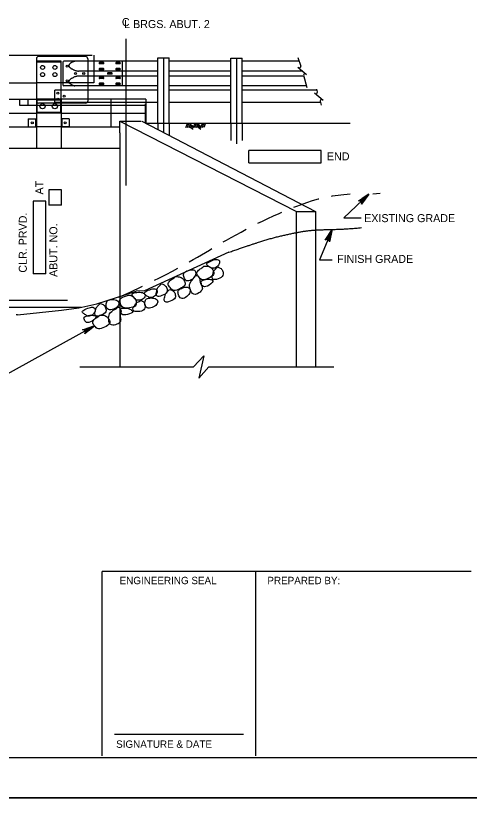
# Model space of a CAD drawing. Extents: x 638268 to 640277, y 295465 to 298435.
# Drawn here: x 638721.7 to 638891.9, y 297240 to 297540.5 of the extents above; entities that cross this region are included whole.
import ezdxf

# ---------------------------------------------------------------- set-up
doc = ezdxf.new("R2010")
doc.units = 0
for name, color, linetype in [('10', 7, 'Continuous'), ('2', 7, 'Continuous'), ('3', 7, 'Continuous'), ('4', 7, 'Continuous'), ('8', 7, 'Continuous'), ('Level 25', 7, 'Continuous'), ('PLT-BNDY', 7, 'Continuous')]:
    doc.layers.add(name, color=color, linetype=linetype)

msp = doc.modelspace()

# ---------------------------------------------------------------- linework, layer by layer
at = {"layer": '2'}
for p, q in [((638577.23, 297525.9), (638750.23, 297525.9)), ((638750.88, 297525.9), (638750.88, 297523.59)), ((638738.57, 297523.59), (638729.33, 297523.59)), ((638729.33, 297523.59), (638729.33, 297509.34)), ((638738.57, 297523.21), (638729.33, 297523.21)), ((638738.57, 297509.34), (638738.57, 297523.59)), ((638739.3, 297523.23), (638739.3, 297514.73)), ((638750.88, 297523.6), (638739.67, 297523.6)), ((638761.47, 297523.6), (638750.88, 297523.6)), ((638750.88, 297523.59), (638750.88, 297515.51)), ((638754.49, 297523.09), (638753.02, 297523.09)), ((638760.67, 297523.09), (638759.19, 297523.09)), ((638761.54, 297523.6), (638761.54, 297514.36)), ((638774.81, 297523.6), (638761.54, 297523.6)), ((638802.21, 297523.6), (638779.14, 297523.6)), ((638827.83, 297523.6), (638806.53, 297523.6)), ((638750.88, 297519.91), (638745.14, 297519.91)), ((638774.81, 297519.91), (638750.88, 297519.91)), ((638754.49, 297522.63), (638753.02, 297522.63)), ((638754.49, 297520.88), (638753.02, 297520.88)), ((638754.49, 297520.41), (638753.02, 297520.41)), ((638760.67, 297522.63), (638759.19, 297522.63)), ((638760.67, 297520.88), (638759.19, 297520.88)), ((638760.67, 297520.41), (638759.19, 297520.41)), ((638802.21, 297519.91), (638779.14, 297519.91)), ((638829.15, 297519.91), (638806.53, 297519.91)), ((638750.88, 297518.06), (638745.14, 297518.06)), ((638774.81, 297518.06), (638750.88, 297518.06)), ((638754.49, 297517.55), (638753.02, 297517.55)), ((638754.49, 297517.09), (638753.02, 297517.09)), ((638757.59, 297519.21), (638756.11, 297519.21)), ((638757.59, 297518.75), (638756.11, 297518.75)), ((638760.67, 297517.55), (638759.19, 297517.55)), ((638760.67, 297517.09), (638759.19, 297517.09)), ((638802.21, 297518.06), (638779.14, 297518.06)), ((638829.59, 297518.06), (638806.53, 297518.06)), ((638688.94, 297515.51), (638729.33, 297515.51)), ((638738.57, 297515.51), (638729.33, 297515.51)), ((638748.58, 297515.51), (638738.57, 297515.51)), ((638748.58, 297514.36), (638739.67, 297514.36)), ((638750.88, 297515.51), (638748.58, 297515.51)), ((638774.81, 297514.36), (638748.58, 297514.36)), ((638754.49, 297515.33), (638753.02, 297515.33)), ((638754.49, 297514.87), (638753.02, 297514.87)), ((638760.67, 297515.33), (638759.19, 297515.33)), ((638760.67, 297514.87), (638759.19, 297514.87)), ((638802.21, 297514.36), (638779.14, 297514.36)), ((638830.52, 297514.36), (638806.53, 297514.36)), ((638736.22, 297508.08), (638736.22, 297512.7)), ((638748.58, 297512.7), (638736.22, 297512.7)), ((638774.81, 297512.7), (638748.58, 297512.7)), ((638802.21, 297512.7), (638779.14, 297512.7)), ((638834.45, 297512.7), (638806.53, 297512.7)), ((638688.94, 297509.34), (638729.33, 297509.34)), ((638723.16, 297507.04), (638723.16, 297509.34)), ((638726.25, 297507.04), (638726.25, 297509.34)), ((638738.57, 297509.34), (638729.33, 297509.34)), ((638729.33, 297509.34), (638729.33, 297491.02)), ((638738.41, 297509.06), (638729.52, 297509.06)), ((638729.52, 297509.06), (638729.52, 297504.45)), ((638770.3, 297508.08), (638736.21, 297508.08)), ((638738.41, 297509.06), (638738.41, 297504.45)), ((638770.32, 297509.34), (638738.57, 297509.34)), ((638738.57, 297509.34), (638738.57, 297491.02)), ((638748.58, 297509.34), (638748.58, 297508.68)), ((638774.81, 297508.08), (638770.32, 297508.08)), ((638802.21, 297508.08), (638779.14, 297508.08)), ((638835.9, 297508.08), (638806.53, 297508.08)), ((638770.3, 297507.04), (638723.15, 297507.04)), ((638688.94, 297504.15), (638729.33, 297504.15)), ((638726.24, 297502.05), (638729.33, 297502.05)), ((638726.24, 297502.05), (638726.24, 297498.96)), ((638728.97, 297502.05), (638728.97, 297498.96)), ((638738.57, 297504.15), (638729.33, 297504.15)), ((638729.33, 297502.05), (638729.33, 297498.96)), ((638738.41, 297504.45), (638729.52, 297504.45)), ((638741.66, 297502.05), (638738.57, 297502.05)), ((638738.57, 297502.05), (638738.57, 297498.96)), ((638738.93, 297502.05), (638738.93, 297498.96)), ((638741.66, 297502.05), (638741.66, 297498.96)), ((638726.24, 297498.96), (638729.33, 297498.96)), ((638738.57, 297498.96), (638729.33, 297498.96)), ((638741.66, 297498.96), (638738.57, 297498.96)), ((639261.46, 297262.46), (638475.46, 297262.46))]:
    msp.add_line(p, q, dxfattribs=at)
for centre, radius in [((638731.65, 297521.28), 0.748), ((638736.26, 297521.28), 0.748), ((638740.88, 297521.72), 0.385), ((638731.65, 297518.59), 0.748), ((638736.26, 297518.59), 0.748), ((638740.91, 297516.27), 0.385), ((638743.99, 297518.99), 0.385), ((638747.07, 297518.99), 0.385), ((638737.41, 297511.65), 0.385), ((638739.72, 297510.49), 0.385), ((638731.65, 297506.75), 0.978), ((638736.26, 297506.75), 0.978), ((638737.41, 297509.34), 0.385), ((638727.79, 297500.5), 0.385), ((638740.11, 297500.5), 0.385)]:
    msp.add_circle(centre, radius, dxfattribs=at)
for centre, radius, start, end in [((638739.67, 297523.23), 0.369, 90, 180), ((638742.44, 297521.97), 0.916, 120.3532, 238.6149), ((638744.76, 297519.33), 4.42, 125.3229, 129.0151), ((638742.76, 297522.15), 0.955, 117.3798, 125.3229), ((638756.95, 297494.76), 31.8, 116.5749, 117.3798), ((638743.8, 297521.04), 2.42, 113.6547, 116.5749), ((638745.21, 297517.82), 5.93, 112.3149, 113.6547), ((638767.53, 297463.43), 64.73, 111.9093, 112.3149), ((638744.08, 297521.73), 1.88, 108.4934, 111.9093), ((638746.71, 297513.88), 10.17, 107.0234, 108.4934), ((638753.16, 297522.86), 0.269, 120.8559, 239.1441), ((638754.36, 297522.86), 0.269, 300.8559, 59.1441), ((638759.33, 297522.86), 0.269, 120.8559, 239.1441), ((638760.53, 297522.86), 0.269, 300.8559, 59.1441), ((638745.19, 297524.93), 4.94, 229.2007, 233.1182), ((638742.88, 297521.85), 1.09, 233.1182, 241.475), ((638929.96, 297866.04), 392.83, 241.475, 241.5275), ((638682.44, 297409.64), 126.36, 61.435, 61.5275), ((638687.83, 297419.55), 115.08, 61.2499, 61.435), ((638753.5, 297539.25), 21.45, 241.2499, 241.6785), ((638743.63, 297520.93), 0.644, 241.6785, 249.7671), ((638749.69, 297537.38), 18.18, 249.7671, 251.2889), ((638744.87, 297523.15), 3.14, 251.2889, 252.6389), ((638771.37, 297607.92), 91.96, 252.6389, 252.8885), ((638744.95, 297522.09), 2.16, 252.8885, 261.633), ((638745.37, 297524.93), 5.03, 261.633, 267.3571), ((638753.16, 297520.65), 0.269, 120.8559, 239.1441), ((638754.36, 297520.65), 0.269, 300.8559, 59.1441), ((638759.33, 297520.65), 0.269, 120.8559, 239.1441), ((638760.53, 297520.65), 0.269, 300.8559, 59.1441), ((638742.44, 297516), 0.916, 121.3851, 239.6468), ((638745.19, 297513.04), 4.94, 126.8818, 130.7993), ((638742.88, 297516.12), 1.09, 118.525, 126.8818), ((638929.96, 297171.93), 392.83, 118.4725, 118.525), ((638682.44, 297628.32), 126.36, 298.4725, 298.565), ((638687.83, 297618.42), 115.08, 298.565, 298.7501), ((638753.5, 297498.71), 21.45, 118.3215, 118.7501), ((638743.63, 297517.03), 0.644, 110.2329, 118.3215), ((638749.69, 297500.58), 18.18, 108.7111, 110.2329), ((638744.87, 297514.82), 3.14, 107.3611, 108.7111), ((638771.37, 297430.05), 91.96, 107.1115, 107.3611), ((638744.95, 297515.88), 2.16, 98.367, 107.1115), ((638745.37, 297513.03), 5.03, 92.6429, 98.367), ((638753.16, 297517.32), 0.269, 120.8559, 239.1441), ((638754.36, 297517.32), 0.269, 300.8559, 59.1441), ((638756.25, 297518.98), 0.269, 120.8559, 239.1441), ((638757.45, 297518.98), 0.269, 300.8559, 59.1441), ((638759.33, 297517.32), 0.269, 120.8559, 239.1441), ((638760.53, 297517.32), 0.269, 300.8559, 59.1441), ((638739.67, 297514.73), 0.369, 180, 270), ((638744.76, 297518.64), 4.42, 230.9849, 234.6771), ((638742.76, 297515.81), 0.955, 234.6771, 242.6202), ((638756.95, 297543.2), 31.8, 242.6202, 243.4251), ((638743.8, 297516.92), 2.42, 243.4251, 246.3453), ((638745.21, 297520.14), 5.93, 246.3453, 247.6851), ((638767.53, 297574.53), 64.73, 247.6851, 248.0907), ((638744.08, 297516.23), 1.88, 248.0907, 251.5066), ((638746.71, 297524.09), 10.17, 251.5066, 252.9766), ((638753.16, 297515.1), 0.269, 120.8559, 239.1441), ((638754.36, 297515.1), 0.269, 300.8559, 59.1441), ((638759.33, 297515.1), 0.269, 120.8559, 239.1441), ((638760.53, 297515.1), 0.269, 300.8559, 59.1441)]:
    msp.add_arc(centre, radius, start, end, dxfattribs=at)
at = {"layer": '3'}
for p, q in [((638774.81, 297524.87), (638779.14, 297524.87)), ((638774.81, 297500.4), (638774.81, 297524.87)), ((638776.98, 297524.87), (638776.98, 297496.9)), ((638779.14, 297500.4), (638779.14, 297524.87)), ((638802.21, 297524.79), (638806.53, 297524.79)), ((638802.21, 297500.4), (638802.21, 297524.79)), ((638804.37, 297524.79), (638804.37, 297492.7)), ((638806.53, 297500.4), (638806.53, 297524.79)), ((638827.39, 297524.97), (638828.4, 297521.82)), ((638827.34, 297521.43), (638830.6, 297518.69)), ((638829.52, 297518.35), (638830.67, 297513.75)), ((638833.58, 297511.71), (638836.84, 297508.97)), ((638834.33, 297513.09), (638834.64, 297512.09)), ((638757.31, 297498.96), (638757.31, 297509.34)), ((638770.32, 297509.34), (638770.32, 297500.4)), ((638835.76, 297508.63), (638836.14, 297507.12)), ((638770.25, 297500.4), (638770.25, 297507.61)), ((638738.55, 297504.15), (638770.32, 297504.15)), ((638688.94, 297498.96), (638729.33, 297498.96)), ((638738.57, 297498.96), (638760.65, 297498.96)), ((638760.65, 297501.12), (638826.85, 297467.24)), ((638760.65, 297496.79), (638760.65, 297501.12)), ((638760.65, 297501.12), (638768.58, 297501.12)), ((638768.86, 297501.12), (638833.99, 297467.24)), ((638770.25, 297500.4), (638846.91, 297500.4)), ((638774.81, 297500.4), (638774.81, 297498.02)), ((638779.14, 297500.4), (638779.14, 297495.77)), ((638785.94, 297500.4), (638785.27, 297498.64)), ((638785.94, 297500.4), (638785.27, 297498.64)), ((638786.49, 297500.41), (638785.82, 297498.65)), ((638786.49, 297500.41), (638785.82, 297498.65)), ((638787.13, 297500.42), (638786.46, 297498.66)), ((638787.13, 297500.42), (638786.46, 297498.66)), ((638786.66, 297499.19), (638788.16, 297498.16)), ((638786.66, 297499.19), (638788.16, 297498.16)), ((638786.83, 297499.64), (638788.12, 297498.75)), ((638786.83, 297499.64), (638788.12, 297498.75)), ((638786.99, 297500.07), (638788.28, 297499.18)), ((638786.99, 297500.07), (638788.28, 297499.18)), ((638788.75, 297500.42), (638788.1, 297498.68)), ((638788.75, 297500.42), (638788.1, 297498.68)), ((638789.3, 297500.42), (638788.64, 297498.69)), ((638789.3, 297500.42), (638788.64, 297498.69)), ((638789.93, 297500.43), (638789.28, 297498.7)), ((638789.93, 297500.43), (638789.28, 297498.7)), ((638789.47, 297499.21), (638790.97, 297498.17)), ((638789.47, 297499.21), (638790.97, 297498.17)), ((638789.64, 297499.65), (638790.93, 297498.76)), ((638789.64, 297499.65), (638790.93, 297498.76)), ((638789.8, 297500.08), (638791.09, 297499.19)), ((638789.8, 297500.08), (638791.09, 297499.19)), ((638791.56, 297500.43), (638790.91, 297498.69)), ((638791.56, 297500.43), (638790.91, 297498.69)), ((638792.11, 297500.43), (638791.45, 297498.7)), ((638792.11, 297500.43), (638791.45, 297498.7)), ((638792.74, 297500.43), (638792.09, 297498.71)), ((638792.74, 297500.43), (638792.09, 297498.71)), ((638802.21, 297500.4), (638802.21, 297493.91)), ((638806.53, 297500.4), (638806.53, 297493.91)), ((638760.65, 297496.79), (638760.65, 297435.29)), ((638568.29, 297491.02), (638747.07, 297491.02)), ((638568.29, 297491.02), (638760.65, 297491.02)), ((638854.01, 297473.83), (638844.53, 297464.9)), ((638826.85, 297467.24), (638833.99, 297467.24)), ((638826.85, 297459.39), (638826.85, 297467.24)), ((638833.99, 297467.24), (638833.99, 297460.29)), ((638844.53, 297464.9), (638851.13, 297464.9)), ((638833.99, 297460.29), (638833.99, 297409.02)), ((638840.25, 297460.55), (638835.49, 297449.16)), ((638826.85, 297409.02), (638826.85, 297459.39)), ((638801.5, 297452), (638769.91, 297437.52)), ((638835.49, 297449.16), (638840.25, 297449.16)), ((638769.91, 297437.52), (638766.76, 297437.44)), ((638760.65, 297435.29), (638760.65, 297409.02)), ((638574.64, 297431.41), (638746.15, 297431.41)), ((638788.26, 297409.02), (638792.1, 297413.19)), ((638792.1, 297413.19), (638790.18, 297404.84)), ((638745.58, 297409.02), (638788.26, 297409.02)), ((638790.18, 297404.84), (638794.02, 297409.02)), ((638794.02, 297409.02), (638840.85, 297409.02))]:
    msp.add_line(p, q, dxfattribs=at)
for points in [[(638851.46, 297472.11), (638852.14, 297471.39), (638853.95, 297473.78)], [(638838.65, 297458.02), (638839.56, 297457.64), (638840.25, 297460.55)]]:
    msp.add_lwpolyline(points, close=True, dxfattribs=at)
for centre, radius, start, end in [((638827.9, 297521.65), 0.533, 227.8504, 17.8504), ((638830.04, 297518.47), 0.533, 49.9832, 192.5218), ((638830.04, 297518.47), 0.533, 49.9832, 49.9972), ((638834.14, 297511.93), 0.533, 227.8504, 17.8504), ((638836.28, 297508.75), 0.533, 49.9832, 192.5218), ((638836.28, 297508.74), 0.533, 49.9832, 49.9972), ((638721.7, 297417.02), 11.48, 87.4213, 90)]:
    msp.add_arc(centre, radius, start, end, dxfattribs=at)
for points, degree in [([(638801.5, 297452), (638809.28, 297454.69), (638816.43, 297457.02), (638823.58, 297458.76), (638830.33, 297460.07), (638836.68, 297460.51), (638845.21, 297460.65), (638851.17, 297461.24)], 2), ([(638793.37, 297447.17), (638793.61, 297446.91), (638794.48, 297446.36), (638795.58, 297445.72), (638797.56, 297446.65), (638798.32, 297448.58), (638797.24, 297449.49), (638795.21, 297449.05), (638793.04, 297447.91), (638793.13, 297447.43), (638793.37, 297447.17)], 3), ([(638784.73, 297444.27), (638784.45, 297443.9), (638784.49, 297443.07), (638785.11, 297441.24), (638786.96, 297441.1), (638788.7, 297442.73), (638789.4, 297444.36), (638788.43, 297445.7), (638786.16, 297445.29), (638785.01, 297444.64), (638784.73, 297444.27)], 3), ([(638791.96, 297446.61), (638791.9, 297446.53), (638791.57, 297446.24), (638789.98, 297445.33), (638789.19, 297443.89), (638790.19, 297442.84), (638791.39, 297441.21), (638793.97, 297442.22), (638796.19, 297443.63), (638795.64, 297445.23), (638794.86, 297446.35), (638793.25, 297446.96), (638791.9, 297446.75), (638792.01, 297446.7), (638791.96, 297446.61)], 3), ([(638795.49, 297443.67), (638795.42, 297443.37), (638795.12, 297443), (638795.27, 297441.78), (638796.62, 297441.61), (638799.51, 297442.86), (638799.42, 297444.62), (638798.9, 297445.72), (638797.64, 297446.42), (638796.99, 297446.46), (638796.69, 297445.84), (638795.52, 297444.81), (638795.56, 297443.97), (638795.49, 297443.67)], 3), ([(638781.18, 297442.63), (638781.13, 297442.55), (638780.79, 297442.26), (638779.21, 297441.34), (638778.41, 297439.91), (638779.42, 297438.86), (638780.62, 297437.23), (638783.2, 297438.23), (638785.42, 297439.65), (638784.87, 297441.24), (638784.08, 297442.37), (638782.48, 297442.98), (638781.13, 297442.77), (638781.24, 297442.72), (638781.18, 297442.63)], 3), ([(638789.05, 297443.31), (638788.91, 297443.22), (638788.8, 297442.76), (638786.54, 297440.45), (638786.79, 297438.24), (638788.19, 297435.65), (638790.38, 297436.66), (638791.8, 297438.17), (638791.33, 297439.54), (638790.57, 297440.56), (638790.72, 297442.4), (638789.63, 297443.3), (638789.19, 297443.4), (638789.05, 297443.31)], 3), ([(638791.5, 297441.39), (638791.08, 297441.24), (638790.78, 297441.14), (638791.48, 297439.08), (638793.2, 297438.91), (638796.32, 297441.37), (638794.48, 297441.9), (638793.29, 297442), (638791.92, 297441.53), (638791.5, 297441.39)], 3), ([(638774.47, 297437.38), (638774.4, 297437.08), (638774.1, 297436.71), (638774.25, 297435.49), (638775.59, 297435.32), (638778.49, 297436.57), (638778.39, 297438.32), (638777.88, 297439.42), (638776.62, 297440.13), (638775.97, 297440.16), (638775.67, 297439.55), (638774.49, 297438.52), (638774.53, 297437.68), (638774.47, 297437.38)], 3), ([(638782.63, 297437.72), (638782.35, 297437.35), (638782.39, 297436.52), (638783.01, 297434.69), (638784.85, 297434.55), (638786.6, 297436.18), (638787.3, 297437.81), (638786.33, 297439.15), (638784.06, 297438.74), (638782.91, 297438.09), (638782.63, 297437.72)], 3), ([(638763.77, 297435.87), (638763.68, 297435.8), (638763.28, 297435.64), (638761.48, 297435.29), (638760.26, 297434.19), (638760.87, 297432.88), (638761.48, 297430.94), (638764.24, 297431.06), (638766.8, 297431.67), (638766.8, 297433.36), (638766.42, 297434.68), (638765.1, 297435.77), (638763.76, 297436.02), (638763.85, 297435.93), (638763.77, 297435.87)], 3), ([(638765.28, 297435.94), (638765.43, 297435.61), (638766.07, 297434.81), (638766.9, 297433.84), (638769.08, 297434.08), (638770.43, 297435.66), (638769.69, 297436.87), (638767.64, 297437.11), (638765.21, 297436.74), (638765.14, 297436.26), (638765.28, 297435.94)], 3), ([(638769.98, 297436.19), (638770.22, 297435.93), (638771.09, 297435.38), (638772.19, 297434.73), (638774.18, 297435.67), (638774.93, 297437.6), (638773.85, 297438.51), (638771.83, 297438.07), (638769.65, 297436.92), (638769.74, 297436.45), (638769.98, 297436.19)], 3), ([(638777.53, 297435.26), (638777.47, 297434.96), (638777.16, 297434.59), (638777.31, 297433.37), (638778.66, 297433.2), (638781.55, 297434.45), (638781.46, 297436.21), (638780.95, 297437.31), (638779.69, 297438.01), (638779.03, 297438.04), (638778.73, 297437.43), (638777.56, 297436.4), (638777.6, 297435.56), (638777.53, 297435.26)], 3), ([(638751.53, 297430.01), (638751.46, 297429.71), (638751.16, 297429.34), (638751.31, 297428.12), (638752.66, 297427.95), (638755.55, 297429.2), (638755.46, 297430.95), (638754.94, 297432.06), (638753.68, 297432.76), (638753.03, 297432.79), (638752.73, 297432.18), (638751.56, 297431.15), (638751.6, 297430.31), (638751.53, 297430.01)], 3), ([(638756.08, 297433.88), (638755.7, 297433.62), (638755.46, 297432.82), (638755.46, 297430.89), (638757.16, 297430.16), (638759.34, 297431.13), (638760.53, 297432.45), (638760.05, 297434.03), (638757.77, 297434.38), (638756.47, 297434.14), (638756.08, 297433.88)], 3), ([(638766.15, 297431.94), (638765.99, 297431.67), (638765.59, 297431.43), (638765.33, 297430.22), (638766.55, 297429.62), (638769.69, 297429.87), (638770.17, 297431.56), (638770.05, 297432.76), (638769.08, 297433.84), (638768.48, 297434.08), (638767.99, 297433.6), (638766.55, 297433.01), (638766.31, 297432.2), (638766.15, 297431.94)], 3), ([(638770.6, 297434.49), (638770.21, 297434.23), (638769.98, 297433.43), (638769.98, 297431.49), (638771.68, 297430.77), (638773.85, 297431.73), (638775.05, 297433.06), (638774.56, 297434.63), (638772.28, 297434.99), (638770.98, 297434.75), (638770.6, 297434.49)], 3), ([(638746.73, 297429.28), (638746.97, 297429.02), (638747.84, 297428.47), (638748.94, 297427.83), (638750.93, 297428.76), (638751.68, 297430.69), (638750.6, 297431.59), (638748.58, 297431.16), (638746.4, 297430.02), (638746.49, 297429.54), (638746.73, 297429.28)], 3), ([(638760.03, 297431.44), (638759.87, 297431.4), (638759.62, 297431), (638756.73, 297429.55), (638756.25, 297427.38), (638756.73, 297424.48), (638759.13, 297424.72), (638760.96, 297425.69), (638760.96, 297427.13), (638760.58, 297428.34), (638761.31, 297430.03), (638760.58, 297431.24), (638760.19, 297431.48), (638760.03, 297431.44)], 3), ([(638761.64, 297431.07), (638761.19, 297431.07), (638760.87, 297431.07), (638760.87, 297428.9), (638762.44, 297428.17), (638766.19, 297429.49), (638764.62, 297430.59), (638763.53, 297431.07), (638762.08, 297431.07), (638761.64, 297431.07)], 3), ([(638747.67, 297427.91), (638747.25, 297427.77), (638746.95, 297427.67), (638747.65, 297425.61), (638749.38, 297425.43), (638752.49, 297427.9), (638750.65, 297428.43), (638749.46, 297428.53), (638748.09, 297428.06), (638747.67, 297427.91)], 3), ([(638752.9, 297428.24), (638752.85, 297428.15), (638752.52, 297427.87), (638750.93, 297426.95), (638750.14, 297425.52), (638751.14, 297424.47), (638752.34, 297422.84), (638754.92, 297423.84), (638757.14, 297425.25), (638756.59, 297426.85), (638755.8, 297427.97), (638754.2, 297428.58), (638752.85, 297428.38), (638752.96, 297428.32), (638752.9, 297428.24)], 3)]:
    msp.add_open_spline(points, degree=degree, dxfattribs=at)
at = {"layer": '4'}
for p, q in [((638762.8, 297531.99), (638762.8, 297477.03)), ((638836.14, 297490.17), (638808.99, 297490.17)), ((638808.99, 297485.47), (638808.99, 297490.17)), ((638836.14, 297485.47), (638836.14, 297490.17)), ((638808.99, 297485.47), (638836.14, 297485.47)), ((638734.02, 297475.36), (638734.02, 297469.61)), ((638738.73, 297475.36), (638734.02, 297475.36)), ((638738.73, 297469.61), (638738.73, 297475.36)), ((638728.18, 297471.1), (638728.18, 297443.95)), ((638732.88, 297471.1), (638728.18, 297471.1)), ((638732.88, 297443.95), (638732.88, 297471.1)), ((638738.73, 297469.61), (638734.02, 297469.61)), ((638732.88, 297443.95), (638728.18, 297443.95)), ((638710.19, 297434.04), (638741.01, 297434.04)), ((638751.11, 297424.45), (638710.89, 297402.22)), ((638754.05, 297263.21), (638754.05, 297332.31)), ((638892.25, 297332.31), (638754.05, 297332.31)), ((638811.64, 297263.21), (638811.64, 297332.31)), ((638807.03, 297271.29), (638758.66, 297271.29))]:
    msp.add_line(p, q, dxfattribs=at)
for points in [[(638854.01, 297473.83), (638851.22, 297470), (638851.31, 297470.43), (638851.23, 297470.78), (638851.05, 297471.05), (638850.8, 297471.24), (638850.45, 297471.34), (638850.02, 297471.27), (638854.01, 297473.83), (638850.45, 297471.34), (638850.8, 297471.24), (638854.01, 297473.83), (638851.05, 297471.05), (638851.23, 297470.78), (638854.01, 297473.83), (638851.31, 297470.43)], [(638840.25, 297460.55), (638839.26, 297455.91), (638839.16, 297456.34), (638838.95, 297456.63), (638838.68, 297456.8), (638838.37, 297456.87), (638838.01, 297456.82), (638837.64, 297456.59), (638840.25, 297460.55), (638838.01, 297456.82), (638838.37, 297456.87), (638840.25, 297460.55), (638838.68, 297456.8), (638838.95, 297456.63), (638840.25, 297460.55), (638839.16, 297456.34)], [(638722.22, 297428.49), (638738.73, 297430.34), (638745.18, 297431.17), (638751.94, 297432.73), (638766.76, 297437.44)], [(638751.11, 297424.45), (638747.49, 297421.39), (638747.67, 297421.78), (638747.68, 297422.15), (638747.57, 297422.45), (638747.37, 297422.69), (638747.06, 297422.87), (638746.62, 297422.91), (638751.11, 297424.45), (638747.06, 297422.87), (638747.37, 297422.69), (638751.11, 297424.45), (638747.57, 297422.45), (638747.68, 297422.15), (638751.11, 297424.45), (638747.67, 297421.78)]]:
    msp.add_lwpolyline(points, dxfattribs=at)
msp.add_lwpolyline([(638748.29, 297423.42), (638748.78, 297422.56), (638751.11, 297424.45)], close=True, dxfattribs=at)
at = {"layer": '8'}
for p, q in [((638832.88, 297471.39), (638835.12, 297472.04)), ((638835.12, 297472.04), (638835.17, 297472.05)), ((638839.98, 297473.07), (638840.31, 297473.13)), ((638840.31, 297473.13), (638843.41, 297473.57)), ((638843.41, 297473.57), (638846.93, 297473.92)), ((638855.4, 297473.92), (638858.22, 297474.11)), ((638825.86, 297468.85), (638826.61, 297469.15)), ((638826.61, 297469.15), (638828.69, 297469.94)), ((638828.69, 297469.94), (638830.76, 297470.69)), ((638830.76, 297470.69), (638832.88, 297471.39)), ((638816.12, 297464.65), (638818.21, 297465.61)), ((638818.21, 297465.61), (638820.31, 297466.54)), ((638820.31, 297466.54), (638821.31, 297466.97)), ((638812.38, 297462.85), (638814.04, 297463.67)), ((638814.04, 297463.67), (638816.12, 297464.65)), ((638804.17, 297458.57), (638806.06, 297459.59)), ((638806.06, 297459.59), (638807.99, 297460.62)), ((638799.37, 297455.87), (638800.57, 297456.56)), ((638800.57, 297456.56), (638802.34, 297457.56)), ((638802.34, 297457.56), (638804.17, 297458.57)), ((638789.68, 297450.18), (638791.21, 297451.08)), ((638791.21, 297451.08), (638792.7, 297451.96)), ((638792.7, 297451.96), (638794.18, 297452.84)), ((638794.18, 297452.84), (638795.12, 297453.39)), ((638786.63, 297448.42), (638788.09, 297449.25)), ((638788.09, 297449.25), (638789.68, 297450.18)), ((638777.94, 297443.69), (638780.39, 297444.97)), ((638780.39, 297444.97), (638782.33, 297446.02)), ((638773.59, 297441.49), (638775.2, 297442.29)), ((638775.2, 297442.29), (638777.94, 297443.69)), ((638764.68, 297437.21), (638768.61, 297439.06)), ((638768.61, 297439.06), (638769.17, 297439.33)), ((638760.25, 297435.18), (638764.68, 297437.21))]:
    msp.add_line(p, q, dxfattribs=at)
at = {"layer": 'Level 25'}
for p, q in [((638729.34, 297524.56), (638729.34, 297523.59)), ((638747.81, 297525.33), (638730.11, 297525.33)), ((638748.58, 297524.56), (638748.58, 297523.59)), ((638748.58, 297523.59), (638748.58, 297514.36)), ((638748.58, 297514.36), (638748.58, 297509.34)), ((638747.81, 297507.91), (638730.11, 297507.91))]:
    msp.add_line(p, q, dxfattribs=at)
for centre, start, end in [((638730.11, 297524.56), 90, 180), ((638747.81, 297524.56), 0, 90), ((638730.11, 297508.68), 180, 270), ((638747.81, 297508.68), 270, 0)]:
    msp.add_arc(centre, 0.77, start, end, dxfattribs=at)
at = {"layer": 'PLT-BNDY'}
for points in [[(638435.46, 297841.46), (639276.46, 297841.46), (639276.46, 297247.46), (638435.46, 297247.46)], [(638435.46, 297247.46), (639276.46, 297247.46), (639276.46, 296653.46), (638435.46, 296653.46)]]:
    msp.add_lwpolyline(points, close=True, dxfattribs=at)

# ---------------------------------------------------------------- texts
at = {"layer": '10'}
for s, p in [('ENGINEERING SEAL', (638760.53, 297327.59)), ('PREPARED BY:', (638815.93, 297327.59)), ('SIGNATURE & DATE', (638759.23, 297266.25))]:
    msp.add_text(s, height=2.7634, dxfattribs=at).set_placement(p)
at = {"layer": '4'}
for s, p in [('C', (638761.38, 297536.78)), ('L BRGS. ABUT. 2', (638762.24, 297536.04)), ('END', (638838.24, 297486.46)), ('EXISTING GRADE', (638852.2, 297463.29)), ('FINISH GRADE', (638842.04, 297448))]:
    msp.add_text(s, height=3, dxfattribs=at).set_placement(p)
for s, p in [('AT', (638731.94, 297473.65)), ('CLR. PRVD.', (638725.74, 297444.35)), ('ABUT. NO. ', (638737.2, 297442.75))]:
    msp.add_text(s, height=3, rotation=90, dxfattribs=at).set_placement(p)

doc.saveas('drawing.dxf')
